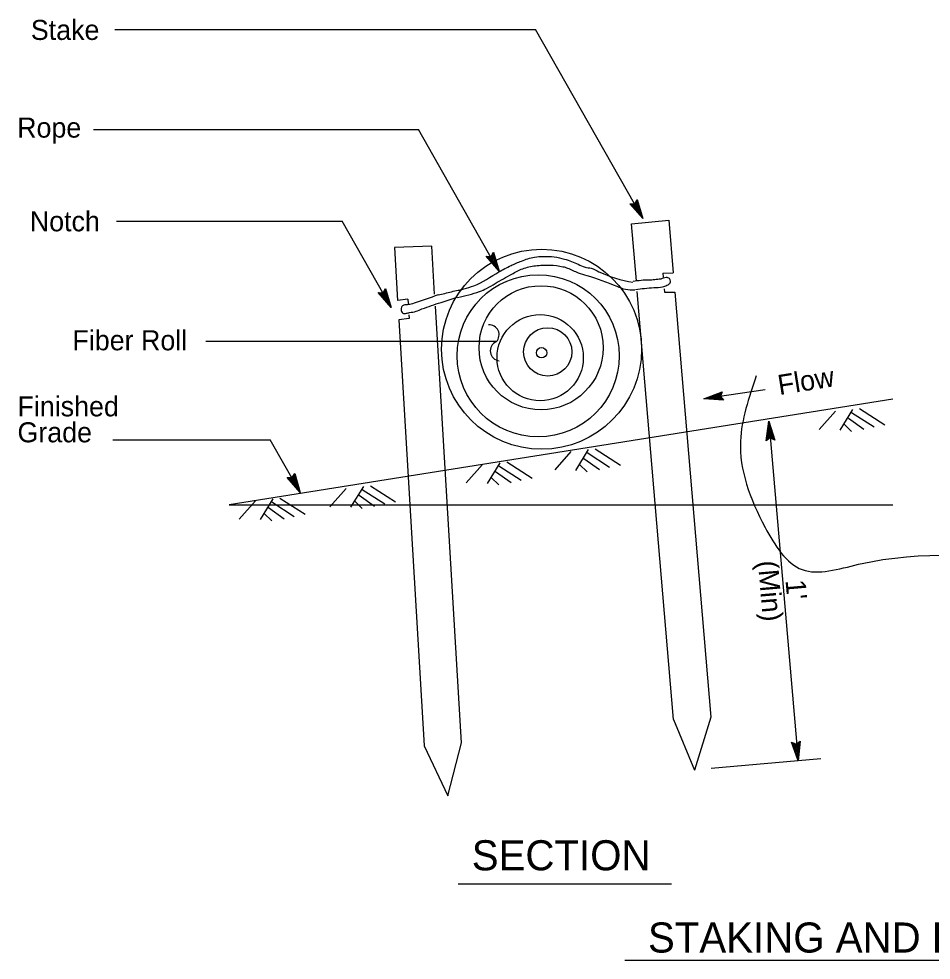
# Model space of a CAD drawing. Extents: x 6707415 to 6708768, y 1869893 to 1870831.
# Drawn here: x 6707415.4 to 6707688.3, y 1870548 to 1870829.6 of the extents above; entities that cross this region are included whole.
import ezdxf

# ---------------------------------------------------------------- set-up
doc = ezdxf.new("R2010")
doc.units = 0
for name, color, linetype in [('56 Stg 3 Anno', 7, 'Continuous'), ('57 Undefined', 7, 'Continuous'), ('58 Soundwalls', 7, 'Continuous'), ('60 Nongeo Data', 7, 'Continuous')]:
    doc.layers.add(name, color=color, linetype=linetype)

msp = doc.modelspace()

# ---------------------------------------------------------------- linework, layer by layer
at = {"layer": '56 Stg 3 Anno'}
for p, q in [((6707444.05, 1870826.4), (6707569.9, 1870826.4)), ((6707602.02, 1870769.81), (6707569.9, 1870826.4)), ((6707437.75, 1870796.48), (6707534.91, 1870796.48)), ((6707558.9, 1870754.22), (6707534.91, 1870796.48)), ((6707599.64, 1870774.2), (6707600.41, 1870775.49)), ((6707600.41, 1870775.49), (6707600.41, 1870775.49)), ((6707600.41, 1870775.49), (6707602.02, 1870769.81)), ((6707602.02, 1870769.81), (6707598.15, 1870774.27)), ((6707598.15, 1870774.27), (6707598.15, 1870774.27)), ((6707598.15, 1870774.27), (6707599.64, 1870774.2)), ((6707601.38, 1870770.98), (6707598.56, 1870774.23)), ((6707600.76, 1870772.15), (6707598.94, 1870774.24)), ((6707600.13, 1870773.31), (6707599.35, 1870774.21)), ((6707599.8, 1870774.47), (6707600.13, 1870773.31)), ((6707600.01, 1870774.78), (6707600.76, 1870772.15)), ((6707600.2, 1870775.14), (6707601.39, 1870770.98)), ((6707602.02, 1870769.81), (6707602.02, 1870769.81)), ((6707444.58, 1870769.01), (6707512.1, 1870769.01)), ((6707526.72, 1870743.26), (6707512.1, 1870769.01)), ((6707559.03, 1870754.09), (6707555.16, 1870758.55)), ((6707555.16, 1870758.55), (6707555.16, 1870758.55)), ((6707555.16, 1870758.55), (6707556.65, 1870758.48)), ((6707558.39, 1870755.27), (6707555.57, 1870758.51)), ((6707557.77, 1870756.43), (6707555.94, 1870758.52)), ((6707557.13, 1870757.59), (6707556.35, 1870758.49)), ((6707556.65, 1870758.48), (6707557.41, 1870759.77)), ((6707556.8, 1870758.76), (6707557.13, 1870757.59)), ((6707557.01, 1870759.06), (6707557.77, 1870756.43)), ((6707557.21, 1870759.42), (6707558.4, 1870755.26)), ((6707557.41, 1870759.77), (6707557.41, 1870759.77)), ((6707557.41, 1870759.77), (6707559.03, 1870754.09)), ((6707559.03, 1870754.09), (6707559.03, 1870754.09)), ((6707522.85, 1870747.72), (6707522.85, 1870747.72)), ((6707526.72, 1870743.26), (6707522.85, 1870747.71)), ((6707522.85, 1870747.71), (6707524.34, 1870747.65)), ((6707526.08, 1870744.43), (6707523.26, 1870747.68)), ((6707525.46, 1870745.59), (6707523.63, 1870747.69)), ((6707524.82, 1870746.76), (6707524.04, 1870747.66)), ((6707524.34, 1870747.65), (6707525.1, 1870748.94)), ((6707524.49, 1870747.92), (6707524.82, 1870746.76)), ((6707524.7, 1870748.23), (6707525.46, 1870745.59)), ((6707524.9, 1870748.59), (6707526.09, 1870744.43)), ((6707525.1, 1870748.94), (6707525.1, 1870748.94)), ((6707525.1, 1870748.94), (6707526.72, 1870743.26)), ((6707526.72, 1870743.26), (6707526.72, 1870743.26)), ((6707471.36, 1870733.12), (6707558.14, 1870733.12)), ((6707638.63, 1870718.62), (6707620.31, 1870715.87)), ((6707620.31, 1870715.87), (6707625.82, 1870717.99)), ((6707621.63, 1870716.08), (6707625.64, 1870717.62)), ((6707622.93, 1870716.26), (6707625.53, 1870717.26)), ((6707625.67, 1870716.07), (6707622.93, 1870716.26)), ((6707624.24, 1870716.46), (6707625.35, 1870716.89)), ((6707625.45, 1870716.37), (6707624.24, 1870716.46)), ((6707625.82, 1870717.99), (6707625.25, 1870716.61)), ((6707625.25, 1870716.61), (6707626.2, 1870715.46)), ((6707625.82, 1870717.99), (6707625.82, 1870717.99)), ((6707626.2, 1870715.46), (6707620.31, 1870715.87)), ((6707620.31, 1870715.87), (6707620.31, 1870715.87)), ((6707625.94, 1870715.76), (6707621.62, 1870716.07)), ((6707626.2, 1870715.46), (6707626.2, 1870715.46)), ((6707638.95, 1870703.32), (6707639.77, 1870709.17)), ((6707639.28, 1870703.56), (6707639.87, 1870707.85)), ((6707639.77, 1870709.17), (6707648.49, 1870607.58)), ((6707639.77, 1870709.17), (6707639.77, 1870709.17)), ((6707639.77, 1870709.17), (6707641.51, 1870703.53)), ((6707639.88, 1870707.84), (6707641.15, 1870703.73)), ((6707639.6, 1870703.81), (6707639.98, 1870706.52)), ((6707639.92, 1870704), (6707640.09, 1870705.2)), ((6707639.98, 1870706.52), (6707640.8, 1870703.87)), ((6707640.09, 1870705.2), (6707640.44, 1870704.07)), ((6707443.52, 1870703.62), (6707490.6, 1870703.62)), ((6707499.52, 1870687.92), (6707490.6, 1870703.62)), ((6707640.17, 1870704.19), (6707638.95, 1870703.32)), ((6707638.95, 1870703.32), (6707638.95, 1870703.32)), ((6707641.51, 1870703.53), (6707640.17, 1870704.19)), ((6707641.51, 1870703.53), (6707641.51, 1870703.53)), ((6707497.13, 1870692.31), (6707497.9, 1870693.59)), ((6707497.9, 1870693.59), (6707497.9, 1870693.59)), ((6707497.9, 1870693.59), (6707499.52, 1870687.92)), ((6707499.52, 1870687.92), (6707495.65, 1870692.37)), ((6707495.65, 1870692.37), (6707495.65, 1870692.37)), ((6707495.65, 1870692.37), (6707497.13, 1870692.31)), ((6707498.88, 1870689.09), (6707496.06, 1870692.34)), ((6707498.25, 1870690.25), (6707496.43, 1870692.35)), ((6707497.62, 1870691.42), (6707496.84, 1870692.31)), ((6707497.29, 1870692.58), (6707497.62, 1870691.42)), ((6707497.5, 1870692.89), (6707498.25, 1870690.25)), ((6707497.7, 1870693.25), (6707498.88, 1870689.08)), ((6707499.52, 1870687.92), (6707499.52, 1870687.92)), ((6707648.49, 1870607.58), (6707646.56, 1870613.16)), ((6707646.56, 1870613.16), (6707646.56, 1870613.16)), ((6707646.56, 1870613.16), (6707647.92, 1870612.54)), ((6707648.33, 1870608.9), (6707646.93, 1870612.97)), ((6707648.19, 1870610.21), (6707647.28, 1870612.84)), ((6707648.04, 1870611.53), (6707647.65, 1870612.65)), ((6707647.92, 1870612.54), (6707649.11, 1870613.45)), ((6707648.16, 1870612.73), (6707648.04, 1870611.53)), ((6707648.47, 1870612.94), (6707648.19, 1870610.21)), ((6707648.79, 1870613.2), (6707648.34, 1870608.9)), ((6707649.11, 1870613.45), (6707648.49, 1870607.58)), ((6707649.11, 1870613.45), (6707649.11, 1870613.45)), ((6707655.28, 1870608.16), (6707622.49, 1870605.35)), ((6707648.49, 1870607.58), (6707648.49, 1870607.58))]:
    msp.add_line(p, q, dxfattribs=at)
for centre, radius, start, end in [((6707556.1, 1870735.07), 2.96, 316.6026, 93.4449), ((6707559.39, 1870730.25), 2.99, 113.9481, 264.448)]:
    msp.add_arc(centre, radius, start, end, dxfattribs=at)
at = {"layer": '57 Undefined'}
for p, q in [((6707478.33, 1870684.16), (6707676.81, 1870684.16)), ((6707546.83, 1870570.79), (6707610.62, 1870570.79)), ((6707596.65, 1870547.96), (6707799.02, 1870547.96))]:
    msp.add_line(p, q, dxfattribs=at)
at = {"layer": '58 Soundwalls'}
for p, q in [((6707659.66, 1870712.16), (6707654.79, 1870706.68)), ((6707664.82, 1870712.74), (6707661.01, 1870706.5)), ((6707664.48, 1870711.83), (6707671.23, 1870707.49)), ((6707666.92, 1870712.96), (6707674.46, 1870708.11)), ((6707662.25, 1870708.31), (6707664.5, 1870706.13)), ((6707663.55, 1870710.12), (6707668.19, 1870706.8)), ((6707580.56, 1870700.13), (6707575.69, 1870694.64)), ((6707585.72, 1870700.7), (6707581.91, 1870694.46)), ((6707585.38, 1870699.79), (6707592.13, 1870695.46)), ((6707587.82, 1870700.92), (6707595.37, 1870696.07)), ((6707559.27, 1870696.79), (6707555.46, 1870690.55)), ((6707561.37, 1870697.02), (6707568.91, 1870692.17)), ((6707584.45, 1870698.08), (6707589.09, 1870694.76)), ((6707554.11, 1870696.22), (6707549.24, 1870690.73)), ((6707558, 1870694.18), (6707562.64, 1870690.85)), ((6707558.93, 1870695.88), (6707565.68, 1870691.55)), ((6707583.15, 1870696.27), (6707585.4, 1870694.09)), ((6707556.7, 1870692.36), (6707558.95, 1870690.18)), ((6707513.29, 1870689.11), (6707508.42, 1870683.63)), ((6707518.45, 1870689.68), (6707514.64, 1870683.45)), ((6707518.11, 1870688.77), (6707524.86, 1870684.44)), ((6707520.55, 1870689.91), (6707528.09, 1870685.06)), ((6707486.2, 1870685.41), (6707481.33, 1870679.93)), ((6707491.36, 1870685.99), (6707487.55, 1870679.75)), ((6707493.46, 1870686.21), (6707501.01, 1870681.36)), ((6707515.88, 1870685.25), (6707518.13, 1870683.07)), ((6707517.17, 1870687.07), (6707521.82, 1870683.74)), ((6707490.09, 1870683.37), (6707494.73, 1870680.04)), ((6707491.02, 1870685.08), (6707497.77, 1870680.74)), ((6707488.79, 1870681.56), (6707491.04, 1870679.37))]:
    msp.add_line(p, q, dxfattribs=at)
at = {"layer": '60 Nongeo Data'}
for p, q in [((6707598.7, 1870768.2), (6707609.79, 1870769.38)), ((6707600.14, 1870751.18), (6707598.7, 1870768.2)), ((6707609.79, 1870769.38), (6707611.12, 1870753.56)), ((6707538.91, 1870761.56), (6707527.77, 1870761.13)), ((6707539.76, 1870747.22), (6707538.91, 1870761.56)), ((6707527.77, 1870761.13), (6707528.71, 1870745.28)), ((6707608.02, 1870753.52), (6707611.12, 1870753.56)), ((6707608.02, 1870753.52), (6707608.13, 1870752.27)), ((6707611.22, 1870619.97), (6707600.4, 1870748.03)), ((6707608.42, 1870748.85), (6707608.51, 1870747.79)), ((6707608.51, 1870747.79), (6707611.61, 1870747.82)), ((6707611.61, 1870747.82), (6707622.35, 1870620.61)), ((6707531.79, 1870745.69), (6707528.71, 1870745.28)), ((6707531.79, 1870745.69), (6707531.86, 1870744.44)), ((6707547.77, 1870613.02), (6707539.98, 1870743.59)), ((6707532.13, 1870739.95), (6707529.06, 1870739.54)), ((6707529.06, 1870739.54), (6707536.66, 1870612.1)), ((6707532.07, 1870741.01), (6707532.13, 1870739.95)), ((6707676.81, 1870715.76), (6707478.33, 1870684.16)), ((6707622.35, 1870620.61), (6707617.55, 1870604.81)), ((6707611.22, 1870619.97), (6707617.55, 1870604.81)), ((6707536.66, 1870612.1), (6707543.67, 1870597.15)), ((6707543.67, 1870597.15), (6707547.77, 1870613.02))]:
    msp.add_line(p, q, dxfattribs=at)
for centre, radius in [((6707571.77, 1870730.74), 29.92), ((6707570.76, 1870728.75), 24.25), ((6707571.62, 1870731.17), 18.57), ((6707571.34, 1870728.19), 12.9), ((6707573.6, 1870729.95), 7.23), ((6707571.77, 1870729.68), 1.55)]:
    msp.add_circle(centre, radius, dxfattribs=at)
for centre, radius, start, end in [((6707604.39, 1870786.2), 35.81, 244.4249, 261.4246), ((6707598.95, 1870759.14), 10.65, 243.7792, 273.8847)]:
    msp.add_arc(centre, radius, start, end, dxfattribs=at)
for points in [[(6707548.55, 1870748.8), (6707551.51, 1870749.71), (6707558.97, 1870753.86), (6707562.62, 1870755.76), (6707565.78, 1870757.12), (6707569.62, 1870758.27), (6707572.37, 1870758.5), (6707575.48, 1870758.35), (6707578.65, 1870757.72), (6707582.68, 1870756.16), (6707584.77, 1870755.31), (6707586.61, 1870754.94), (6707588.93, 1870753.9)], [(6707546.66, 1870746.18), (6707553.23, 1870748.01), (6707555.3, 1870748.9), (6707557.89, 1870750.42), (6707562.85, 1870753.2), (6707566.12, 1870754.81), (6707569.94, 1870755.7), (6707574.2, 1870755.88), (6707578.16, 1870755.43), (6707579.5, 1870755.01), (6707582.69, 1870753.62), (6707585.28, 1870752.83), (6707594.24, 1870749.59)], [(6707599.84, 1870748.59), (6707605.36, 1870749.17), (6707607.97, 1870749.44), (6707609.25, 1870749.87), (6707609.95, 1870750.25), (6707610.31, 1870751.11), (6707610.01, 1870751.87), (6707609.07, 1870752.17), (6707607.43, 1870751.74), (6707605.62, 1870751.54), (6707604.74, 1870751.41), (6707603.89, 1870751.41), (6707599.19, 1870751)], [(6707540.78, 1870746.99), (6707544.77, 1870747.94), (6707546.83, 1870748.41), (6707547.89, 1870748.56), (6707548.55, 1870748.8)], [(6707540.78, 1870746.99), (6707533.6, 1870744.48), (6707531.87, 1870744.08), (6707530.59, 1870743.92), (6707529.85, 1870743.29), (6707529.73, 1870742.57), (6707530.24, 1870741.56), (6707531.31, 1870741.5), (6707532.28, 1870741.69), (6707534.22, 1870742.09), (6707535.98, 1870742.8)], [(6707535.98, 1870742.8), (6707541.69, 1870744.74), (6707546.55, 1870746.26)], [(6707636.01, 1870722.73), (6707631.26, 1870703.25), (6707638.65, 1870677.44), (6707649.72, 1870664.81), (6707666.6, 1870666.39), (6707721.99, 1870667.44), (6707994.19, 1870675.34), (6708114.47, 1870677.97)]]:
    msp.add_spline(points, degree=3, dxfattribs=at)

# ---------------------------------------------------------------- texts
at = {"layer": '57 Undefined'}
for s, height, p in [('Stake', 6, (6707418.97, 1870823.26)), ('Rope', 6, (6707414.87, 1870794.04)), ('Notch', 6, (6707418.66, 1870766.01)), ('Fiber Roll', 6, (6707431.42, 1870730.41)), ('Finished', 6, (6707414.97, 1870710.65)), ('Grade', 6, (6707414.97, 1870702.88)), ('SECTION', 9, (6707550.87, 1870574.84)), ('STAKING AND LASHING DETAIL', 9, (6707603.59, 1870550.24))]:
    msp.add_text(s, height=height, dxfattribs=at).set_placement(p)
for s, rotation, p in [('Flow', 9.1077, (6707642.93, 1870717)), ('(Min)', 274.9064, (6707636.45, 1870667.29)), ("1'", 274.9064, (6707644.74, 1870661.57))]:
    msp.add_text(s, height=6, rotation=rotation, dxfattribs=at).set_placement(p)

doc.saveas('drawing.dxf')
